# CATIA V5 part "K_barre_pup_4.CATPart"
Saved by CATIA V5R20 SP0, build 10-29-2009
Part number: barre_pup_4
Bounding box of the stored display mesh (mm): x -85.893 to -73.814, y -211.469 to -6.5, z -166.022 to -156.458
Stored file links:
  G:\Khaled_CFAO_2011\ST2M\ST2M_GR2\gcausse\Khaled\CAD_ThinkMotion\K_barre_pup_4.CATPart
  C:\Documents and Settings\gcausse\Bureau\video thinkmotio\assemblage_gcausse\pupitre_think.CATProduct
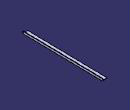
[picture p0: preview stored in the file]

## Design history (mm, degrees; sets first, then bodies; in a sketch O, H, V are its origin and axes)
Set1
  Sketch1 on Plane1, origin (-53.7378, 0, 6.6108), H (0, 1, 0), V (0.1221, 0, 0.9925)
    line L1 (-8.9561, -167.9349) -> (-208.9252, -164.4216)
    arc A1 centre (-208.9691, -166.9212) radius 2.5 from (-208.9252, -164.4216) to (-209.0131, -169.4208) ccw
    point P3 (-208.9691, -166.9212)
    line L2 (-209.0131, -169.4208) -> (-9.0439, -172.9342)
    arc A2 centre (-9, -170.4346) radius 2.5 from (-9.0439, -172.9342) to (-8.9561, -167.9349) ccw
    point P6 (-9, -170.4346)
    reference projected point E1 (-9, -170.4346) from Point1
    reference projected point E2 (-208.9691, -166.9212) from Point2
    reference projected line E3 (-9, -170.4346) -> (-208.9691, -166.9212) from Line1
    reference projected line E4 (-9, -170.4346) -> (-208.9691, -166.9212) from Line1
    distance L1 L2 = 5
    tangency: A1 L1, L2 A1, A2 L1, A2 L2
    coincidence: P6 E1, P3 E2
    parallelism: L1 E3, E4 L2
Set2
  Plane1: linked copy from another document
  Point1: linked copy from another document
  Point2: linked copy from another document
  Line1: linked copy from another document
  Point3: linked copy from another document
Body1 (main body)
  Pad1: profile Sketch1, direction (0.9925, 0, -0.1221), length -1
  Sketch2 on face of Pad1 from Sketch1.L2, origin (-74.4239, -209.0131, -161.5424), H (-0.0021, 0.9998, -0.0174), V (-0.9925, 0, 0.1221)
    point P1 (200, 0)
    line L1 (200, 0) -> (0, 0)
    line L2 (0, 0) -> (0, 1)
    line L3 (0, 1) -> (200, 1)
    line L4 (200, 1) -> (200, 0)
    reference projected line E1 (0, 0) -> (200, 0) from edge [face of Pad1 from Sketch1.L2 | start face of Pad1]
    reference projected line E2 (0, 1) -> (200, 1) from edge [end face of Pad1 | face of Pad1 from Sketch1.L2]
    reference projected point E3 (0, 1) from Point3
    reference projected line E4 (200, 0) -> (200, 1) from edge [face of Pad1 from Sketch1.L2 | face of Pad1 from Sketch1.A2]
    coincidence: P1 H, L1 E1, L3 E2, L2 E3, L4 E4
    vertical: L2 V, L4 V
  Pad2: profile Sketch2, direction (-0.1221, -0.0176, -0.9924), length 1
  Sketch3 on face of Pad2, origin (-54.7303, 0, 6.7329), H (0, 1, 0), V (0.1221, 0, 0.9925)
    line L1 (-9.0615, -173.934) -> (-209.0306, -170.4207)
    line L2 (-209.0306, -170.4207) -> (-209.0131, -169.4208)
    line L3 (-209.0131, -169.4208) -> (-9.0439, -172.9342)
    line L4 (-9.0439, -172.9342) -> (-9.0615, -173.934)
    reference projected line E1 (-9.0615, -173.934) -> (-209.0306, -170.4207) from edge [end face of Pad2 | face of Pad2 from Sketch2.L3]
    reference projected line E2 (-209.0131, -169.4208) -> (-209.0306, -170.4207) from edge [face of Pad2 | face of Pad2 from Sketch2.L2]
    length L4 = 1
    length L2 = 1
    coincidence: L1 E1, L2 E2
    parallelism: L3 L1
  Pad3: profile Sketch3, direction (-0.9925, 0, 0.1221), length 10
  Sketch4 on face of Pad2, origin (-75.2099, -204.0962, -159.7412), H (0.1221, 0, 0.9925), V (0, 1, 0)
    point P1 (0.8079, -4.8729)
    reference projected point E1 (0.8079, -4.8729) from Point2
    coincidence: P1 E1
  Hole1: placed by Sketch4, at (-75.1113, -208.9691, -158.9394) direction (0.9925, 0, -0.1221), diameter 1, depth 1
  Sketch5 on face of Pad2, origin (-75.5943, -16.9953, -162.8659), H (0.1221, 0, 0.9925), V (0, 1, 0)
    point P1 (0.4428, 7.9953)
    reference projected point E1 (0.4428, 7.9953) from Point1
    coincidence: P1 E1
  Hole2: placed by Sketch5, at (-75.5402, -9, -162.4264) direction (0.9925, 0, -0.1221), diameter 1, depth 1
